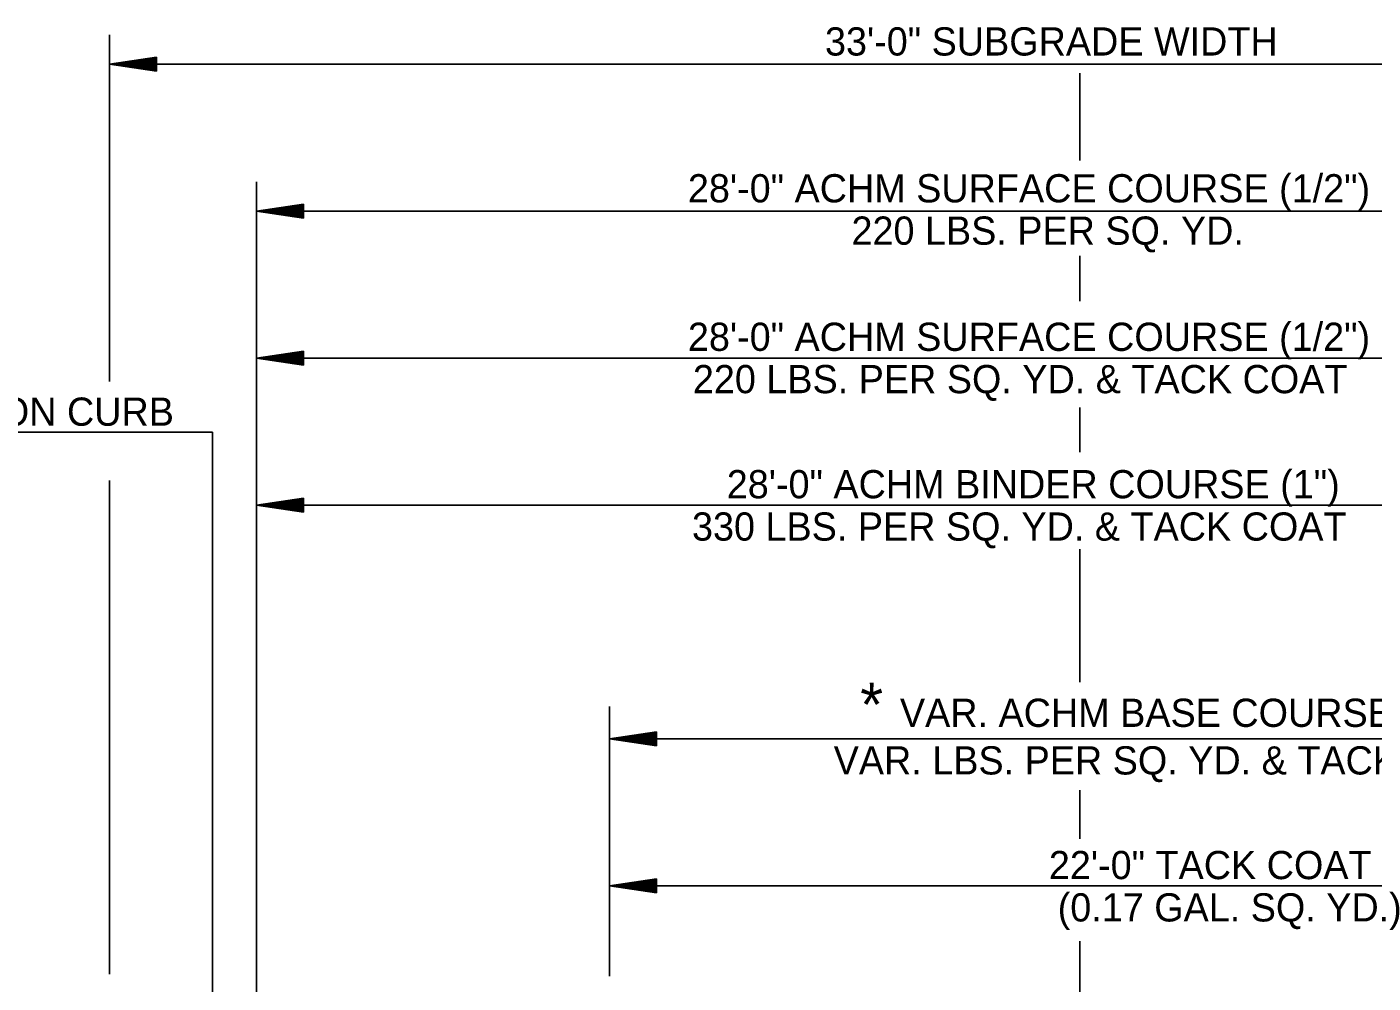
# Model space of a CAD drawing. Extents: x 634177 to 635904, y 289936 to 290970.
# Drawn here: x 635679.73 to 635708.34, y 290468.36 to 290488.69 of the extents above; entities that cross this region are included whole.
import ezdxf

# ---------------------------------------------------------------- set-up
doc = ezdxf.new("R2010")
doc.units = 0
for name, color, linetype in [('Level 13', 7, 'Continuous'), ('Level 2', 7, 'Continuous'), ('Level 43', 7, 'Continuous'), ('R_Dimension', 7, 'Continuous')]:
    doc.layers.add(name, color=color, linetype=linetype)

msp = doc.modelspace()

# ---------------------------------------------------------------- linework, layer by layer
at = {"layer": 'Level 2'}
for p, q in [((635702.111, 290485.854), (635702.111, 290487.708)), ((635702.111, 290482.863), (635702.111, 290483.827)), ((635702.111, 290479.653), (635702.111, 290480.602)), ((635702.111, 290474.763), (635702.111, 290477.593)), ((635702.111, 290471.43), (635702.111, 290472.467)), ((635702.111, 290458.566), (635702.111, 290469.255))]:
    msp.add_line(p, q, dxfattribs=at)
at = {"layer": 'Level 43'}
for p, q in [((635681.486, 290481.151), (635681.486, 290488.527)), ((635722.736, 290487.902), (635681.486, 290487.902)), ((635684.611, 290459.366), (635684.611, 290485.402)), ((635719.611, 290484.777), (635684.611, 290484.777)), ((635719.611, 290481.652), (635684.611, 290481.652)), ((635683.673, 290480.076), (635669.739, 290480.076)), ((635683.673, 290467.305), (635683.673, 290480.076)), ((635681.486, 290468.551), (635681.486, 290479.051)), ((635719.611, 290478.527), (635684.611, 290478.527)), ((635692.111, 290468.508), (635692.111, 290474.245)), ((635719.611, 290473.555), (635692.111, 290473.555)), ((635719.611, 290470.43), (635692.111, 290470.43))]:
    msp.add_line(p, q, dxfattribs=at)
at = {"layer": 'R_Dimension'}
for p, q in [((635682.486, 290488.052), (635681.486, 290487.902)), ((635682.486, 290488.027), (635681.653, 290487.902)), ((635682.486, 290488.001), (635681.825, 290487.902)), ((635682.486, 290487.752), (635682.486, 290488.052)), ((635682.486, 290487.752), (635681.486, 290487.902)), ((635682.486, 290487.777), (635681.653, 290487.902)), ((635682.486, 290487.802), (635681.825, 290487.902)), ((635682.486, 290487.976), (635681.991, 290487.902)), ((635682.486, 290487.827), (635681.991, 290487.902)), ((635682.486, 290487.951), (635682.161, 290487.902)), ((635682.486, 290487.853), (635682.161, 290487.902)), ((635682.486, 290487.925), (635682.328, 290487.902)), ((635682.486, 290487.878), (635682.328, 290487.902)), ((635685.611, 290484.927), (635684.611, 290484.777)), ((635685.611, 290484.902), (635684.778, 290484.777)), ((635685.611, 290484.876), (635684.95, 290484.777)), ((635685.611, 290484.851), (635685.116, 290484.777)), ((635685.611, 290484.627), (635685.611, 290484.927)), ((635685.611, 290484.627), (635684.611, 290484.777)), ((635685.611, 290484.652), (635684.778, 290484.777)), ((635685.611, 290484.677), (635684.95, 290484.777)), ((635685.611, 290484.702), (635685.116, 290484.777)), ((635685.611, 290484.826), (635685.286, 290484.777)), ((635685.611, 290484.728), (635685.286, 290484.777)), ((635685.611, 290484.8), (635685.453, 290484.777)), ((635685.611, 290484.753), (635685.453, 290484.777)), ((635685.611, 290481.802), (635684.611, 290481.652)), ((635685.611, 290481.777), (635684.778, 290481.652)), ((635685.611, 290481.751), (635684.95, 290481.652)), ((635685.611, 290481.726), (635685.116, 290481.652)), ((635685.611, 290481.701), (635685.286, 290481.652)), ((635685.611, 290481.502), (635685.611, 290481.802)), ((635685.611, 290481.502), (635684.611, 290481.652)), ((635685.611, 290481.527), (635684.778, 290481.652)), ((635685.611, 290481.552), (635684.95, 290481.652)), ((635685.611, 290481.577), (635685.116, 290481.652)), ((635685.611, 290481.603), (635685.286, 290481.652)), ((635685.611, 290481.675), (635685.453, 290481.652)), ((635685.611, 290481.628), (635685.453, 290481.652)), ((635685.611, 290478.677), (635684.611, 290478.527)), ((635685.611, 290478.652), (635684.778, 290478.527)), ((635685.611, 290478.626), (635684.95, 290478.527)), ((635685.611, 290478.601), (635685.116, 290478.527)), ((635685.611, 290478.576), (635685.286, 290478.527)), ((635685.611, 290478.55), (635685.453, 290478.527)), ((635685.611, 290478.377), (635685.611, 290478.677)), ((635685.611, 290478.377), (635684.611, 290478.527)), ((635685.611, 290478.402), (635684.778, 290478.527)), ((635685.611, 290478.427), (635684.95, 290478.527)), ((635685.611, 290478.452), (635685.116, 290478.527)), ((635685.611, 290478.478), (635685.286, 290478.527)), ((635685.611, 290478.503), (635685.453, 290478.527)), ((635693.111, 290473.705), (635692.111, 290473.555)), ((635693.111, 290473.68), (635692.278, 290473.555)), ((635693.111, 290473.405), (635693.111, 290473.705)), ((635693.111, 290473.405), (635692.111, 290473.555)), ((635693.111, 290473.43), (635692.278, 290473.555)), ((635693.111, 290473.655), (635692.45, 290473.555)), ((635693.111, 290473.456), (635692.45, 290473.555)), ((635693.111, 290473.63), (635692.616, 290473.555)), ((635693.111, 290473.481), (635692.616, 290473.555)), ((635693.111, 290473.604), (635692.786, 290473.555)), ((635693.111, 290473.507), (635692.786, 290473.555)), ((635693.111, 290473.579), (635692.953, 290473.555)), ((635693.111, 290473.532), (635692.953, 290473.555)), ((635693.111, 290470.58), (635692.111, 290470.43)), ((635693.111, 290470.555), (635692.278, 290470.43)), ((635693.111, 290470.53), (635692.45, 290470.43)), ((635693.111, 290470.28), (635693.111, 290470.58)), ((635693.111, 290470.28), (635692.111, 290470.43)), ((635693.111, 290470.305), (635692.278, 290470.43)), ((635693.111, 290470.331), (635692.45, 290470.43)), ((635693.111, 290470.505), (635692.616, 290470.43)), ((635693.111, 290470.356), (635692.616, 290470.43)), ((635693.111, 290470.479), (635692.786, 290470.43)), ((635693.111, 290470.382), (635692.786, 290470.43)), ((635693.111, 290470.454), (635692.953, 290470.43)), ((635693.111, 290470.407), (635692.953, 290470.43))]:
    msp.add_line(p, q, dxfattribs=at)

# ---------------------------------------------------------------- texts
at = {"layer": 'Level 13'}
for s, height, p in [('33\'-0" SUBGRADE WIDTH', 0.6, (635696.692, 290488.084)), ('28\'-0" ACHM SURFACE COURSE (1/2")', 0.6, (635693.779, 290484.962)), ('220 LBS. PER SQ. YD.', 0.6, (635697.256, 290484.062)), ('28\'-0" ACHM SURFACE COURSE (1/2")', 0.6, (635693.779, 290481.805)), ('220 LBS. PER SQ. YD. & TACK COAT', 0.6, (635693.885, 290480.905)), ('CONCRETE COMBINATION CURB', 0.6, (635669.973, 290480.213)), ('28\'-0" ACHM BINDER COURSE (1")', 0.6, (635694.605, 290478.671)), ('330 LBS. PER SQ. YD. & TACK COAT', 0.6, (635693.866, 290477.771)), ('*', 0.931, (635697.442, 290473.82)), ('VAR. ACHM BASE COURSE (1 1/2")', 0.6, (635698.285, 290473.811)), ('VAR. LBS. PER SQ. YD. & TACK COATS', 0.6, (635696.877, 290472.799)), ('22\'-0" TACK COAT', 0.6, (635701.451, 290470.574)), ('(0.17 GAL. SQ. YD.)', 0.6, (635701.638, 290469.674))]:
    msp.add_text(s, height=height, dxfattribs=at).set_placement(p)

doc.saveas('drawing.dxf')
